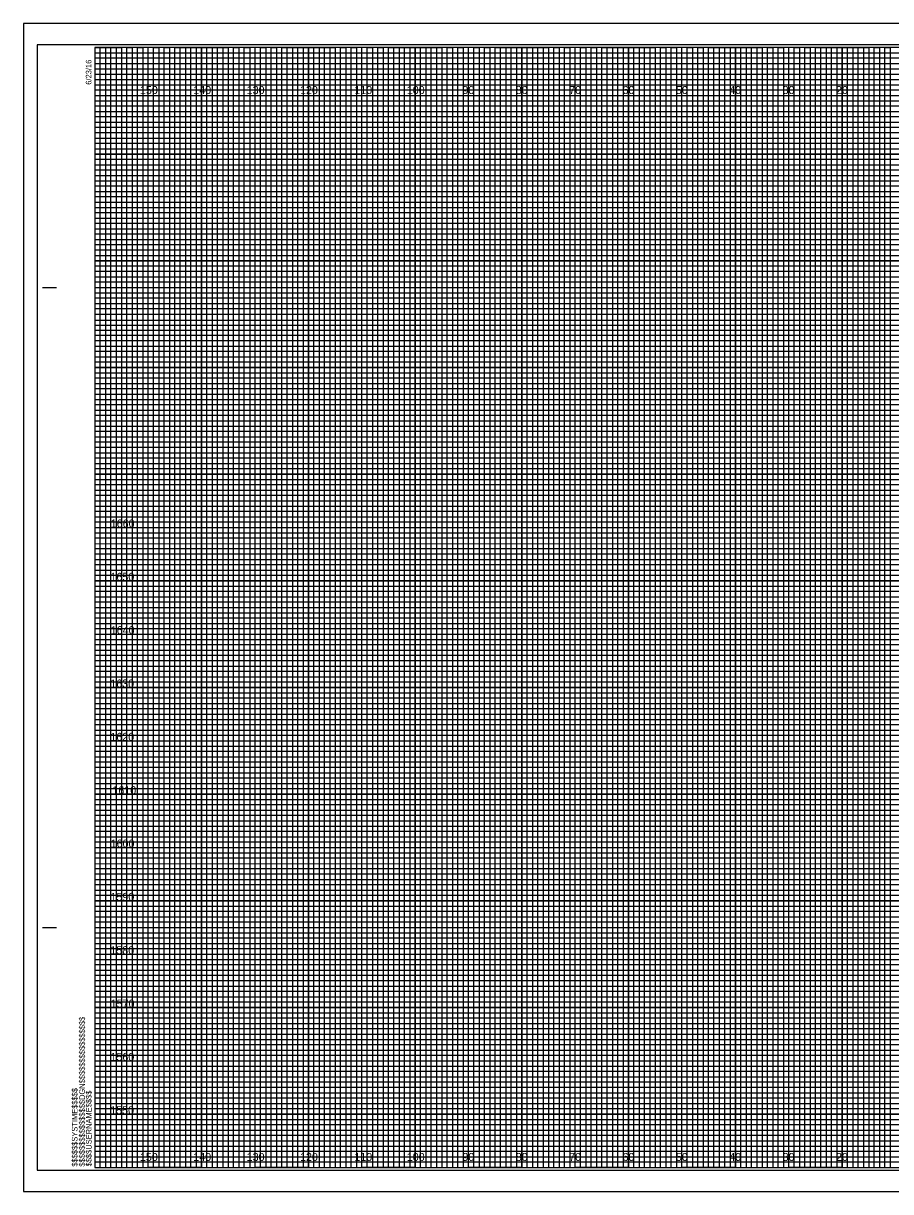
# Model space of a CAD drawing. Extents: x -13 to 323, y 215 to 434.
# Drawn here: x -13.4 to 149.1, y 215.5 to 434.5 of the extents above; entities that cross this region are included whole.
import ezdxf

# ---------------------------------------------------------------- set-up
doc = ezdxf.new("R2010")
doc.units = 0
for name, color, linetype in [('Exist Cross Section Cell', 7, 'Continuous'), ('Exist XS Center Line Elevation Label', 7, 'Continuous'), ('Exist XS Ground Line', 7, 'Continuous'), ('Prop XS Finish Grade', 7, 'Continuous'), ('Prop XS Finish Grade Earthwork', 7, 'Continuous'), ('Prop XS Finish Grade Pavement', 7, 'Continuous'), ('Prop XS SE Text', 7, 'Continuous'), ('Prop XS Side Slope Text', 7, 'Continuous'), ('Scratch_Level_5', 7, 'Continuous'), ('Typical Curb CELL', 7, 'Continuous'), ('Typical Guardrail CELL', 7, 'Continuous')]:
    doc.layers.add(name, color=color, linetype=linetype)

msp = doc.modelspace()

# ---------------------------------------------------------------- linework, layer by layer
at = {"layer": 'Exist Cross Section Cell'}
for points in [[(0, 430), (5, 430), (5, 220), (15, 220), (15, 430), (25, 430), (25, 220), (35, 220), (35, 430), (45, 430), (45, 220), (55, 220), (55, 430), (65, 430), (65, 220), (75, 220), (75, 430), (85, 430), (85, 220), (95, 220), (95, 430), (105, 430), (105, 220), (115, 220), (115, 430), (125, 430), (125, 220), (135, 220), (135, 430), (145, 430), (145, 220), (155, 220)], [(0, 425), (275, 425)], [(0, 405), (320, 405), (320, 415), (0, 415)], [(0, 385), (320, 385), (320, 395), (0, 395)], [(0, 365), (320, 365), (320, 375), (0, 375)], [(0, 345), (320, 345), (320, 355), (0, 355)], [(0, 325), (320, 325), (320, 335), (0, 335)], [(0, 305), (320, 305), (320, 315), (0, 315)], [(0, 285), (320, 285), (320, 295), (0, 295)], [(0, 265), (320, 265), (320, 275), (0, 275)], [(0, 245), (320, 245), (320, 255), (0, 255)], [(0, 225), (320, 225), (320, 235), (0, 235)]]:
    msp.add_lwpolyline(points, dxfattribs=at)
at = {"layer": 'Exist XS Center Line Elevation Label'}
for p, q in [((10, 430), (0, 430)), ((10, 220), (10, 430)), ((30, 430), (20, 430)), ((20, 430), (20, 220)), ((30, 220), (30, 430)), ((50, 430), (40, 430)), ((40, 430), (40, 220)), ((50, 220), (50, 430)), ((70, 430), (60, 430)), ((60, 430), (60, 220)), ((70, 220), (70, 430)), ((90, 430), (80, 430)), ((80, 430), (80, 220)), ((90, 220), (90, 430)), ((110, 430), (100, 430)), ((100, 430), (100, 220)), ((110, 220), (110, 430)), ((130, 430), (120, 430)), ((120, 430), (120, 220)), ((130, 220), (130, 430)), ((150, 430), (140, 430)), ((140, 430), (140, 220)), ((20, 220), (10, 220)), ((40, 220), (30, 220)), ((60, 220), (50, 220)), ((80, 220), (70, 220)), ((100, 220), (90, 220)), ((120, 220), (110, 220)), ((140, 220), (130, 220))]:
    msp.add_line(p, q, dxfattribs=at)
for points in [[(0, 420), (320, 420), (320, 410), (0, 410)], [(0, 400), (320, 400), (320, 390), (0, 390)], [(0, 380), (320, 380), (320, 370), (0, 370)], [(0, 360), (320, 360), (320, 350), (0, 350)], [(0, 340), (320, 340), (320, 330), (0, 330)], [(0, 320), (320, 320), (320, 310), (0, 310)], [(0, 300), (320, 300), (320, 290), (0, 290)], [(0, 280), (320, 280), (320, 270), (0, 270)], [(0, 260), (320, 260), (320, 250), (0, 250)], [(0, 240), (320, 240), (320, 230), (0, 230)]]:
    msp.add_lwpolyline(points, dxfattribs=at)
at = {"layer": 'Prop XS Finish Grade'}
msp.add_lwpolyline([(-10.8, 219.5), (322.4, 219.5), (322.4, 430.5), (-10.8, 430.5)], close=True, dxfattribs=at)
at = {"layer": 'Prop XS Finish Grade Earthwork'}
for p, q in [((10, 220), (10, 430)), ((20, 220), (20, 430)), ((30, 220), (30, 430)), ((40, 220), (40, 430)), ((50, 220), (50, 430)), ((60, 220), (60, 430)), ((70, 220), (70, 430)), ((80, 220), (80, 430)), ((90, 220), (90, 430)), ((100, 220), (100, 430)), ((110, 220), (110, 430)), ((120, 220), (120, 430)), ((130, 220), (130, 430)), ((140, 220), (140, 430)), ((0, 420), (320, 420)), ((0, 410), (320, 410)), ((0, 400), (320, 400)), ((0, 390), (320, 390)), ((0, 380), (320, 380)), ((0, 370), (320, 370)), ((0, 360), (320, 360)), ((0, 350), (320, 350)), ((0, 340), (320, 340)), ((0, 330), (320, 330)), ((0, 320), (320, 320)), ((0, 310), (320, 310)), ((0, 300), (320, 300)), ((0, 290), (320, 290)), ((0, 280), (320, 280)), ((0, 270), (320, 270)), ((0, 260), (320, 260)), ((0, 250), (320, 250)), ((0, 240), (320, 240)), ((0, 230), (320, 230))]:
    msp.add_line(p, q, dxfattribs=at)
at = {"layer": 'Prop XS Finish Grade Pavement'}
for points in [[(0, 220), (1, 220), (1, 430), (2, 430), (2, 220)], [(2, 220), (3, 220), (3, 430), (4, 430), (4, 220)], [(5, 220), (6, 220), (6, 430), (7, 430), (7, 220)], [(7, 220), (8, 220), (8, 430), (9, 430), (9, 220)], [(10, 220), (11, 220), (11, 430), (12, 430), (12, 220)], [(12, 220), (13, 220), (13, 430), (14, 430), (14, 220)], [(15, 220), (16, 220), (16, 430), (17, 430), (17, 220)], [(17, 220), (18, 220), (18, 430), (19, 430), (19, 220)], [(20, 220), (21, 220), (21, 430), (22, 430), (22, 220)], [(22, 220), (23, 220), (23, 430), (24, 430), (24, 220)], [(25, 220), (26, 220), (26, 430), (27, 430), (27, 220)], [(27, 220), (28, 220), (28, 430), (29, 430), (29, 220)], [(30, 220), (31, 220), (31, 430), (32, 430), (32, 220)], [(32, 220), (33, 220), (33, 430), (34, 430), (34, 220)], [(35, 220), (36, 220), (36, 430), (37, 430), (37, 220)], [(37, 220), (38, 220), (38, 430), (39, 430), (39, 220)], [(40, 220), (41, 220), (41, 430), (42, 430), (42, 220)], [(42, 220), (43, 220), (43, 430), (44, 430), (44, 220)], [(45, 220), (46, 220), (46, 430), (47, 430), (47, 220)], [(47, 220), (48, 220), (48, 430), (49, 430), (49, 220)], [(50, 220), (51, 220), (51, 430), (52, 430), (52, 220)], [(52, 220), (53, 220), (53, 430), (54, 430), (54, 220)], [(55, 220), (56, 220), (56, 430), (57, 430), (57, 220)], [(57, 220), (58, 220), (58, 430), (59, 430), (59, 220)], [(60, 220), (61, 220), (61, 430), (62, 430), (62, 220)], [(62, 220), (63, 220), (63, 430), (64, 430), (64, 220)], [(65, 220), (66, 220), (66, 430), (67, 430), (67, 220)], [(67, 220), (68, 220), (68, 430), (69, 430), (69, 220)], [(70, 220), (71, 220), (71, 430), (72, 430), (72, 220)], [(72, 220), (73, 220), (73, 430), (74, 430), (74, 220)], [(75, 220), (76, 220), (76, 430), (77, 430), (77, 220)], [(77, 220), (78, 220), (78, 430), (79, 430), (79, 220)], [(80, 220), (81, 220), (81, 430), (82, 430), (82, 220)], [(82, 220), (83, 220), (83, 430), (84, 430), (84, 220)], [(85, 220), (86, 220), (86, 430), (87, 430), (87, 220)], [(87, 220), (88, 220), (88, 430), (89, 430), (89, 220)], [(90, 220), (91, 220), (91, 430), (92, 430), (92, 220)], [(92, 220), (93, 220), (93, 430), (94, 430), (94, 220)], [(95, 220), (96, 220), (96, 430), (97, 430), (97, 220)], [(97, 220), (98, 220), (98, 430), (99, 430), (99, 220)], [(100, 220), (101, 220), (101, 430), (102, 430), (102, 220)], [(102, 220), (103, 220), (103, 430), (104, 430), (104, 220)], [(105, 220), (106, 220), (106, 430), (107, 430), (107, 220)], [(107, 220), (108, 220), (108, 430), (109, 430), (109, 220)], [(110, 220), (111, 220), (111, 430), (112, 430), (112, 220)], [(112, 220), (113, 220), (113, 430), (114, 430), (114, 220)], [(115, 220), (116, 220), (116, 430), (117, 430), (117, 220)], [(117, 220), (118, 220), (118, 430), (119, 430), (119, 220)], [(120, 220), (121, 220), (121, 430), (122, 430), (122, 220)], [(122, 220), (123, 220), (123, 430), (124, 430), (124, 220)], [(125, 220), (126, 220), (126, 430), (127, 430), (127, 220)], [(127, 220), (128, 220), (128, 430), (129, 430), (129, 220)], [(130, 220), (131, 220), (131, 430), (132, 430), (132, 220)], [(132, 220), (133, 220), (133, 430), (134, 430), (134, 220)], [(135, 220), (136, 220), (136, 430), (137, 430), (137, 220)], [(137, 220), (138, 220), (138, 430), (139, 430), (139, 220)], [(140, 220), (141, 220), (141, 430), (142, 430), (142, 220)], [(142, 220), (143, 220), (143, 430), (144, 430), (144, 220)], [(145, 220), (146, 220), (146, 430), (147, 430), (147, 220)], [(147, 220), (148, 220), (148, 430), (149, 430), (149, 220)]]:
    msp.add_lwpolyline(points, dxfattribs=at)
at = {"layer": 'Prop XS SE Text'}
for p, q in [((-9.8, 385), (-7.3, 385)), ((-9.7, 385), (-7.2, 385)), ((-9.8, 265), (-7.3, 265)), ((-9.7, 265), (-7.2, 265)), ((0, 220), (0, 220)), ((0, 220), (0, 220)), ((0, 220), (0, 220)), ((0, 220), (0, 220)), ((0, 220), (0, 220)), ((0, 220), (0, 220)), ((0, 220), (0, 220))]:
    msp.add_line(p, q, dxfattribs=at)
msp.add_lwpolyline([(320, 430), (0, 430), (0, 220), (320, 220)], close=True, dxfattribs=at)
at = {"layer": 'Scratch_Level_5'}
for p, q in [((0, 429), (260, 429)), ((260, 427.98), (0, 427.98)), ((0, 427.98), (0, 427)), ((0, 427), (260, 427)), ((260, 425.89), (0, 425.89)), ((0, 425.89), (0, 424)), ((0, 424), (320, 424))]:
    msp.add_line(p, q, dxfattribs=at)
for points in [[(0, 423), (270, 423), (320, 423), (320, 422), (0, 422)], [(0, 421), (320, 421), (320, 419), (0, 419)], [(0, 418), (320, 418), (320, 417), (0, 416.98)], [(0, 416), (320, 416), (320, 414), (0, 414)], [(0, 413), (320, 413), (320, 412), (0, 412)], [(0, 411), (320, 411), (320, 409), (0, 409)], [(0, 408), (320, 408), (320, 407), (0, 407)], [(0, 406), (320, 406), (320, 404), (0, 404)], [(0, 403), (320, 403), (320, 402), (0, 402)], [(0, 401), (320, 401), (320, 399), (0, 399)], [(0, 398), (320, 398), (320, 397), (0, 397)], [(0, 396), (320, 396), (320, 393.95), (320, 393), (320, 392), (0, 392)], [(0, 394), (320, 394), (320, 393), (0, 393)], [(0, 391), (320, 391), (320, 389), (0, 389.03)], [(0, 389.03), (320, 389), (320, 388), (0, 388)], [(0, 387), (320, 387), (320, 386), (0, 386)], [(0, 384), (320, 384), (320, 383), (0, 383)], [(0, 382), (320, 382), (320, 381), (0, 381)], [(-0.07, 378.89), (320, 378.89), (320, 377.88), (-0.07, 377.88)], [(0, 377), (320, 377), (320, 376), (0, 376)], [(0, 374), (320, 374), (320, 373), (0, 373)], [(0, 372), (320, 372), (320, 371), (0, 371)], [(0, 369), (320, 369), (320, 368), (0, 368)], [(0, 367), (320, 367), (320, 366), (0, 366)], [(0, 364), (320, 364), (320, 363), (0, 363)], [(0, 362), (320, 362), (320, 361), (0, 361)], [(0, 359), (320, 359), (319.99, 357.98), (0, 358)], [(0, 357), (320, 357), (320, 356), (0, 356)], [(0, 354), (320, 354), (320, 353), (0, 353)], [(0, 352), (320, 352), (320, 351), (0, 351)], [(0, 349), (320, 349), (320, 348), (0, 348)], [(0, 347), (320, 347), (320, 346), (0, 346)], [(0, 344), (320, 344), (320, 343), (0, 343)], [(0, 342), (320, 342), (320, 341), (0, 341)], [(0, 339), (320, 339), (320, 338), (0, 338)], [(0, 336.99), (320.07, 336.91), (320, 336), (0, 336)], [(0, 334), (320, 334), (320, 333), (0, 333)], [(0, 332), (320, 332), (320, 331), (0, 331)], [(0, 329), (320, 329), (320, 328), (0, 328)], [(0, 327), (320, 327), (320, 326), (0, 326)], [(0, 324), (320, 324), (320, 323), (0, 323)], [(0, 322), (320, 322), (320, 321), (0, 321)], [(0, 319), (320, 319), (320, 318), (0, 318)], [(0, 317), (320, 317), (320, 316), (0, 316)], [(0, 314), (320, 314), (320, 313), (0, 313)], [(0, 312), (320, 312), (320, 311), (0, 311)], [(0, 309), (320, 309), (320, 308), (0, 308)], [(0, 307), (320, 307), (320, 306), (0, 306)], [(0, 304), (320, 304), (320, 303), (0, 303)], [(0, 302), (320, 302), (320, 301), (0, 301)], [(0, 299), (320, 299), (319.99, 297.98), (0, 298)], [(0, 297), (320, 297), (320, 296), (0, 296)], [(0, 294), (320, 294), (320, 293), (0, 293)], [(0, 292), (320, 292), (320, 291), (0, 291)], [(0, 289), (320, 289), (320, 288), (0, 288)], [(0, 287), (320, 287), (320, 286), (0, 286)], [(0, 284), (320, 284), (320, 283), (0, 283)], [(0, 282), (320, 282), (320, 281), (0, 281)], [(0, 279), (320, 279), (320, 278), (0, 278)], [(0, 276.99), (320.07, 276.91), (320, 276), (0, 276)], [(0, 274), (320, 274), (320, 273), (0, 273)], [(0, 272), (320, 272), (320, 271), (0, 271)], [(0, 269), (320, 269), (320, 268), (0, 268)], [(0, 267), (320, 267), (320, 266), (0, 266)], [(0, 264), (320, 264), (320, 263), (0, 263)], [(0, 262), (320, 262), (320, 261), (0, 261)], [(0, 259), (320, 259), (320, 258), (0, 258)], [(0, 257), (320, 257), (320, 256), (0, 256)], [(0, 254), (320, 254), (320, 253), (0, 253)], [(0, 252), (320, 252), (320, 251), (0, 251)], [(0, 249), (320, 249), (320, 248), (0, 248)], [(0, 247), (320, 247), (320, 246), (0, 246)], [(0, 244), (320, 244), (320, 243), (0, 243)], [(0, 242), (320, 242), (320, 241), (0, 241)], [(0, 239), (320, 239), (320, 238), (0, 238)], [(0, 237), (320, 237), (320, 236), (0, 236)], [(0, 234), (320, 234), (320, 233), (0, 233)], [(0, 232), (320, 232), (320, 231), (0, 231)], [(0, 229), (320, 229), (320, 228), (0, 228)], [(0, 227), (320, 227), (320, 226), (0, 226)], [(0, 224), (320, 224), (320, 223), (0, 223)], [(0, 222), (320, 222), (320, 221), (0, 221)]]:
    msp.add_lwpolyline(points, dxfattribs=at)
at = {"layer": 'Typical Curb CELL'}
msp.add_lwpolyline([(-13.4, 215.5), (323.3, 215.5), (323.3, 434.5), (-13.4, 434.5)], close=True, dxfattribs=at)
at = {"layer": 'Typical Guardrail CELL'}
for p, q in [((323.3, 434.5), (-13.4, 434.5)), ((-13.4, 434.5), (-13.4, 215.5)), ((-13.4, 215.5), (323.3, 215.5))]:
    msp.add_line(p, q, dxfattribs=at)

# ---------------------------------------------------------------- texts
at = {"layer": 'Exist XS Ground Line'}
for s, p in [('150', (8.44, 421.25)), ('140', (18.44, 421.25)), ('130', (28.44, 421.25)), ('120', (38.44, 421.25)), ('110', (48.62, 421.25)), ('100', (58.44, 421.25)), ('90', (68.86, 421.25)), ('80', (78.86, 421.25)), ('70', (88.86, 421.25)), ('60', (98.86, 421.25)), ('50', (108.86, 421.25)), ('40', (118.86, 421.25)), ('30', (128.86, 421.25)), ('20', (138.86, 421.25)), ('150', (8.44, 221.25)), ('140', (18.44, 221.25)), ('130', (28.44, 221.25)), ('120', (38.44, 221.25)), ('110', (48.62, 221.25)), ('100', (58.44, 221.25)), ('90', (68.86, 221.25)), ('80', (78.86, 221.25)), ('70', (88.86, 221.25)), ('60', (98.86, 221.25)), ('50', (108.86, 221.25)), ('40', (118.86, 221.25)), ('30', (128.86, 221.25)), ('20', (138.86, 221.25))]:
    msp.add_text(s, height=1.5, dxfattribs=at).set_placement(p)
at = {"layer": 'Prop XS SE Text'}
for s, p in [('6/23/16', (-0.65, 423)), ('$$$$$$$$$$$$$$$$DGN$$$$$$$$$$$$$$$$', (-1.88, 220.18)), ('$$$$$$SYSTIME$$$$$', (-3.26, 220.18)), ('$$$$USERNAME$$$$', (-0.62, 220.23))]:
    msp.add_text(s, height=1.05, rotation=90, dxfattribs=at).set_placement(p)
at = {"layer": 'Prop XS Side Slope Text'}
for s, p in [('1660', (2.97, 340)), ('1650', (2.92, 330)), ('1640', (2.97, 320)), ('1630', (2.89, 310)), ('1620', (2.9, 300)), ('1610', (3.28, 290)), ('1600', (2.95, 280)), ('1590', (2.92, 270)), ('1580', (2.9, 260)), ('1570', (2.96, 250)), ('1560', (2.92, 240)), ('1550', (2.87, 230))]:
    msp.add_text(s, height=1.5, dxfattribs=at).set_placement(p)

doc.saveas('drawing.dxf')
